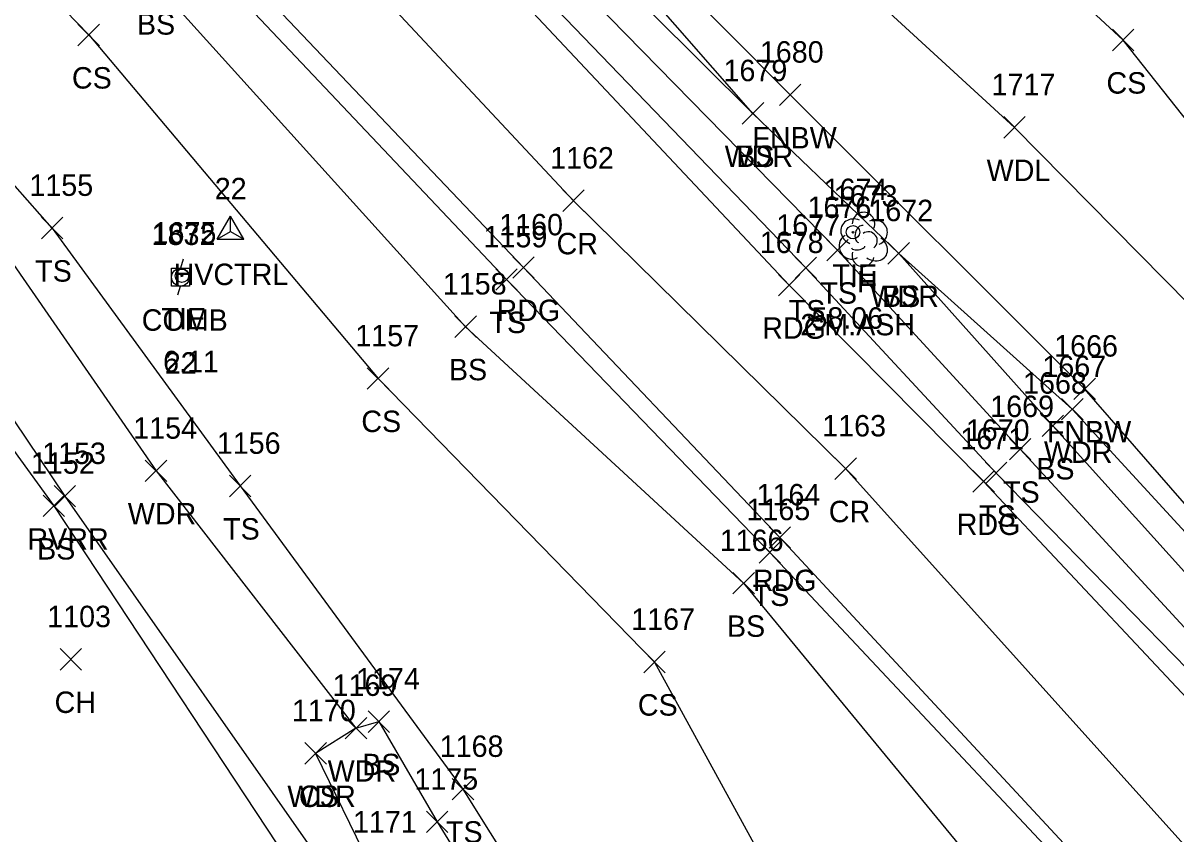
# Model space of a CAD drawing. Extents: x 1469310 to 1475157, y 493997 to 498873.
# Drawn here: x 1469401.2 to 1469508.8, y 498651.4 to 498727 of the extents above; entities that cross this region are included whole.
import ezdxf

# ---------------------------------------------------------------- set-up
doc = ezdxf.new("R2010")
doc.units = 0
for name, color, linetype in [('C_A', 7, 'Continuous'), ('C_C', 7, 'Continuous'), ('C_I', 7, 'Continuous'), ('CBP', 7, 'Continuous'), ('CPSM', 7, 'Continuous'), ('L_A', 7, 'Continuous'), ('L_C', 7, 'Continuous'), ('L_I', 7, 'Continuous'), ('L_TIC', 7, 'Continuous'), ('LAWA', 7, 'Continuous'), ('LAWE', 7, 'Continuous'), ('LELB', 7, 'Continuous'), ('LFNC', 7, 'Continuous'), ('LTD', 7, 'Continuous'), ('P_A', 7, 'Continuous'), ('P_I', 7, 'Continuous'), ('P_TIC', 7, 'Continuous'), ('PEU', 7, 'Continuous'), ('PRC', 7, 'Continuous'), ('U_A', 7, 'Continuous'), ('U_C', 7, 'Continuous'), ('U_I', 7, 'Continuous'), ('UP', 7, 'Continuous')]:
    doc.layers.add(name, color=color, linetype=linetype)

msp = doc.modelspace()

# ---------------------------------------------------------------- linework, layer by layer
at = {"layer": 'CBP'}
for centre, radius in [((1469478.65, 498707.51), 0.625), ((1469478.65, 498707.51), 0.0833), ((1469416.06, 498703.45), 0.625), ((1469416.06, 498703.45), 0.0833)]:
    msp.add_circle(centre, radius, dxfattribs=at)
at = {"layer": 'CPSM'}
for p, q in [((1469419.34, 498706.86), (1469420.59, 498709.02)), ((1469421.84, 498706.86), (1469420.59, 498709.02)), ((1469420.59, 498707.58), (1469420.59, 498709.02)), ((1469419.34, 498706.86), (1469420.59, 498707.58)), ((1469420.59, 498707.58), (1469420.59, 498707.58)), ((1469420.59, 498707.58), (1469421.84, 498706.86)), ((1469419.34, 498706.86), (1469421.84, 498706.86))]:
    msp.add_line(p, q, dxfattribs=at)
at = {"layer": 'L_TIC'}
for points in [[(1469406.36, 498724.91), (1469408.36, 498726.91)], [(1469408.36, 498724.91), (1469406.36, 498726.91)], [(1469502.85, 498724.44), (1469504.85, 498726.44)], [(1469504.85, 498724.44), (1469502.85, 498726.44)], [(1469471.78, 498719.33), (1469473.78, 498721.33)], [(1469473.78, 498719.33), (1469471.78, 498721.33)], [(1469468.32, 498717.6), (1469470.32, 498719.6)], [(1469470.32, 498717.6), (1469468.32, 498719.6)], [(1469468.32, 498717.6), (1469470.32, 498719.6)], [(1469470.32, 498717.6), (1469468.32, 498719.6)], [(1469492.7, 498716.29), (1469494.7, 498718.29)], [(1469494.7, 498716.29), (1469492.7, 498718.29)], [(1469402.96, 498706.9), (1469404.96, 498708.9)], [(1469404.96, 498706.9), (1469402.96, 498708.9)], [(1469476.2, 498704.84), (1469478.2, 498706.84)], [(1469478.2, 498704.84), (1469476.2, 498706.84)], [(1469481.91, 498704.54), (1469483.91, 498706.54)], [(1469483.91, 498704.54), (1469481.91, 498706.54)], [(1469481.91, 498704.54), (1469483.91, 498706.54)], [(1469483.91, 498704.54), (1469481.91, 498706.54)], [(1469473.24, 498703.18), (1469475.24, 498705.18)], [(1469475.24, 498703.18), (1469473.24, 498705.18)], [(1469445.33, 498702.1), (1469447.33, 498704.1)], [(1469447.33, 498702.1), (1469445.33, 498704.1)], [(1469441.52, 498697.7), (1469443.52, 498699.7)], [(1469443.52, 498697.7), (1469441.52, 498699.7)], [(1469433.35, 498692.87), (1469435.35, 498694.87)], [(1469435.35, 498692.87), (1469433.35, 498694.87)], [(1469499.25, 498691.91), (1469501.25, 498693.91)], [(1469501.25, 498691.91), (1469499.25, 498693.91)], [(1469498.1, 498690), (1469500.1, 498692)], [(1469500.1, 498690), (1469498.1, 498692)], [(1469496.29, 498688.45), (1469498.29, 498690.45)], [(1469498.29, 498688.45), (1469496.29, 498690.45)], [(1469493.24, 498686.27), (1469495.24, 498688.27)], [(1469495.24, 498686.27), (1469493.24, 498688.27)], [(1469412.64, 498684.25), (1469414.64, 498686.25)], [(1469414.64, 498684.25), (1469412.64, 498686.25)], [(1469491, 498684.05), (1469493, 498686.05)], [(1469493, 498684.05), (1469491, 498686.05)], [(1469420.49, 498682.84), (1469422.49, 498684.84)], [(1469422.49, 498682.84), (1469420.49, 498684.84)], [(1469404.14, 498681.89), (1469406.14, 498683.89)], [(1469406.14, 498681.89), (1469404.14, 498683.89)], [(1469403.11, 498680.98), (1469405.11, 498682.98)], [(1469405.11, 498680.98), (1469403.11, 498682.98)], [(1469469.89, 498676.65), (1469471.89, 498678.65)], [(1469471.89, 498676.65), (1469469.89, 498678.65)], [(1469467.45, 498673.77), (1469469.45, 498675.77)], [(1469469.45, 498673.77), (1469467.45, 498675.77)], [(1469404.7, 498666.67), (1469406.7, 498668.67)], [(1469406.7, 498666.67), (1469404.7, 498668.67)], [(1469459.14, 498666.42), (1469461.14, 498668.42)], [(1469461.14, 498666.42), (1469459.14, 498668.42)], [(1469431.29, 498660.26), (1469433.29, 498662.26)], [(1469433.29, 498660.26), (1469431.29, 498662.26)], [(1469433.43, 498660.86), (1469435.43, 498662.86)], [(1469435.43, 498660.86), (1469433.43, 498662.86)], [(1469427.53, 498657.9), (1469429.53, 498659.9)], [(1469429.53, 498657.9), (1469427.53, 498659.9)], [(1469427.53, 498657.9), (1469429.53, 498659.9)], [(1469429.53, 498657.9), (1469427.53, 498659.9)], [(1469441.27, 498654.57), (1469443.27, 498656.57)], [(1469443.27, 498654.57), (1469441.27, 498656.57)], [(1469438.87, 498651.51), (1469440.87, 498653.51)], [(1469440.87, 498651.51), (1469438.87, 498653.51)]]:
    msp.add_lwpolyline(points, dxfattribs=at)
at = {"layer": 'LAWA'}
for points in [[(1469550.26, 498635.87), (1469551.34, 498638.82), (1469543.79, 498653.66), (1469517, 498693.69), (1469493.7, 498717.29), (1469464.73, 498743.89), (1469442.45, 498767.36), (1469415.63, 498791.26), (1469396.51, 498809.17), (1469374.23, 498838.07)], [(1469550.26, 498635.87), (1469544.55, 498639.35), (1469529.26, 498656.59), (1469521.27, 498666.89), (1469499.1, 498691), (1469482.91, 498705.54), (1469469.32, 498718.6), (1469451.08, 498739.43), (1469431.27, 498758.58), (1469415.67, 498776.75), (1469392.18, 498799.73), (1469384.54, 498811.21)], [(1469393.99, 498713.68), (1469413.64, 498685.25), (1469432.29, 498661.26), (1469428.53, 498658.9)]]:
    msp.add_lwpolyline(points, dxfattribs=at)
at = {"layer": 'LAWE'}
msp.add_lwpolyline([(1469389.72, 498705.76), (1469405.14, 498682.89), (1469430.85, 498646.13), (1469451.62, 498613.53), (1469475.38, 498586.01), (1469482.32, 498572.69), (1469484.59, 498569.54), (1469489.26, 498567.84), (1469509.66, 498577.17), (1469522.84, 498580.18), (1469533.51, 498579.28), (1469530.31, 498572.64)], dxfattribs=at)
at = {"layer": 'LELB'}
for points in [[(1469689.87, 498657.87), (1469664.2, 498669.39), (1469609.73, 498671.93), (1469582.14, 498658.76), (1469563.4, 498646.02), (1469554.48, 498659.45), (1469546.06, 498676.67), (1469525.38, 498698.23), (1469503.85, 498725.44), (1469472.45, 498754.54), (1469455.13, 498777.29), (1469419.87, 498802.33), (1469400.99, 498819.04), (1469383.05, 498844.76)], [(1469469.32, 498718.6), (1469450.25, 498737.56), (1469430.69, 498757.59), (1469415.11, 498773.82), (1469391.34, 498798.74), (1469366.13, 498825.62)], [(1469596.34, 498559.71), (1469578.35, 498585.4), (1469563.74, 498607.63), (1469555.37, 498620.37), (1469550.82, 498626.65), (1469541.68, 498637.32), (1469517.52, 498662), (1469494.24, 498687.27), (1469477.2, 498705.84), (1469448.36, 498735.3), (1469427.59, 498756.34), (1469413.62, 498771.3), (1469390.02, 498797.18), (1469364.14, 498823.89)], [(1469563.74, 498607.63), (1469555.09, 498616.5), (1469548.65, 498625.25), (1469539.23, 498636.49), (1469516.21, 498660.23), (1469492, 498685.05), (1469474.24, 498704.18), (1469446.06, 498733.49), (1469425.87, 498754.55), (1469411.99, 498769.1), (1469387.95, 498794.99), (1469362.09, 498822.05)], [(1469407.36, 498725.91), (1469385.28, 498748.65)], [(1469416.82, 498734.31), (1469446.33, 498703.1), (1469470.89, 498677.65), (1469509.28, 498636.71), (1469524.42, 498615.8), (1469544.37, 498592.02), (1469564.88, 498563.16), (1469574.6, 498542.86), (1469576.57, 498532.67), (1469562.98, 498525.95), (1469548.2, 498517.37), (1469540.61, 498511.22), (1469554.07, 498484.99), (1469566.51, 498459.59)], [(1469413.42, 498730.94), (1469442.52, 498698.7), (1469468.45, 498674.77), (1469500.53, 498635.82), (1469519, 498614.53), (1469533.17, 498594.86), (1469544.52, 498587.12), (1469562.89, 498554.7), (1469567.79, 498543.52), (1469559.26, 498528.6), (1469545.4, 498521.66), (1469536.79, 498513.03)], [(1469407.36, 498725.91), (1469434.35, 498693.87), (1469460.14, 498667.42), (1469482.37, 498626.84), (1469497.15, 498602.25), (1469503.47, 498589.17)], [(1469403.96, 498707.9), (1469388.97, 498724.88)], [(1469403.96, 498707.9), (1469421.49, 498683.84), (1469442.27, 498655.57), (1469465.35, 498618.65), (1469483.42, 498593.57), (1469487.55, 498583.88), (1469493.17, 498586.36), (1469503.47, 498589.17), (1469519.52, 498592.82), (1469533.17, 498594.86)], [(1469529.26, 498656.59), (1469518.98, 498665.39), (1469497.29, 498689.45), (1469482.91, 498705.54)], [(1469387.88, 498704.33), (1469404.11, 498681.98), (1469428.9, 498644.42), (1469449.54, 498612.82), (1469474.41, 498585.16), (1469480.64, 498571.19), (1469484.92, 498567.97), (1469489.16, 498565.96), (1469510.3, 498575.29), (1469522.97, 498578.34), (1469531.66, 498578.29)], [(1469432.29, 498661.26), (1469434.43, 498661.86)], [(1469434.43, 498661.86), (1469439.87, 498652.51), (1469461.92, 498616.73), (1469481.61, 498592.39), (1469486.84, 498579.65), (1469494.02, 498578.22), (1469506.13, 498583.82), (1469519.69, 498588.79), (1469534.49, 498586.2), (1469541.72, 498579.08), (1469557.44, 498552.67)], [(1469428.53, 498658.9), (1469433.57, 498648.51), (1469459.29, 498614.44), (1469478.33, 498589.06), (1469483.97, 498576.63), (1469489.34, 498572.76), (1469492.49, 498571.98), (1469507.99, 498581.09), (1469520.42, 498585.29), (1469534.63, 498584.29), (1469538.32, 498574.02), (1469547.83, 498560.42), (1469557.44, 498552.67), (1469555.67, 498535.67), (1469539.85, 498524.73), (1469536.79, 498513.03), (1469549.04, 498482.48), (1469564.46, 498458.05), (1469576.5, 498438.75), (1469578.88, 498431.59)]]:
    msp.add_lwpolyline(points, dxfattribs=at)
at = {"layer": 'LFNC'}
msp.add_lwpolyline([(1469557.57, 498626.92), (1469550.26, 498635.87), (1469522.29, 498667.62), (1469500.25, 498692.91), (1469472.78, 498720.33), (1469454.31, 498738.91), (1469435.59, 498759.19), (1469416.3, 498780.92), (1469395.2, 498801.33), (1469384.54, 498811.21), (1469367.12, 498829.45)], dxfattribs=at)
at = {"layer": 'LTD'}
msp.add_line((1469479.59, 498706.89), (1469479.59, 498706.89), dxfattribs=at)
msp.add_line((1469479.59, 498706.89), (1469479.59, 498706.89), dxfattribs=at)
msp.add_arc((1469479.63, 498708.32), 1.05, 335.5272, 180.9563, dxfattribs=at)
for centre, major_axis, ratio, start_param, end_param in [((1469478.8, 498707.55), (1.21, -0.51), 0.895232, 1.570796, 4.712389), ((1469480.63, 498707.47), (-1.14, -0.48), 0.949671, 1.570796, 4.712389), ((1469478.5, 498706.18), (0.58, -1.04), 0.959034, 3.141593, 6.283185), ((1469479.38, 498707.34), (-0.208, -0.792), 0.645439, 3.141593, 6.283185), ((1469480.09, 498706.72), (-0.5, 0.667), 0.989748, 3.141593, 6.283185), ((1469479.13, 498706.14), (-0.625, -0.083), 0.423636, 0, 3.141593), ((1469480.59, 498706.05), (-1.09, 0.79), 0.841452, 1.570796, 4.712389), ((1469479.59, 498705.39), (0.26, 1.06), 0.942809, 1.570796, 4.712389)]:
    msp.add_ellipse(centre, major_axis=major_axis, ratio=ratio, start_param=start_param, end_param=end_param, dxfattribs=at)
at = {"layer": 'P_TIC'}
for points in [[(1469451.57, 498709.45), (1469453.57, 498711.45)], [(1469453.57, 498709.45), (1469451.57, 498711.45)], [(1469446.91, 498703.22), (1469448.91, 498705.22)], [(1469448.91, 498703.22), (1469446.91, 498705.22)], [(1469471.69, 498701.57), (1469473.69, 498703.57)], [(1469473.69, 498701.57), (1469471.69, 498703.57)], [(1469476.96, 498684.46), (1469478.96, 498686.46)], [(1469478.96, 498684.46), (1469476.96, 498686.46)], [(1469489.83, 498683.27), (1469491.83, 498685.27)], [(1469491.83, 498683.27), (1469489.83, 498685.27)], [(1469470.83, 498678.03), (1469472.83, 498680.03)], [(1469472.83, 498678.03), (1469470.83, 498680.03)]]:
    msp.add_lwpolyline(points, dxfattribs=at)
at = {"layer": 'PEU'}
for points in [[(1469787.29, 498391.19), (1469770.79, 498403.19), (1469744.94, 498420.51), (1469711.23, 498443.77), (1469680.07, 498463.21), (1469651.58, 498483.41), (1469630.63, 498501.52), (1469612.52, 498523.24), (1469599.41, 498542.19), (1469591.57, 498556.6), (1469575.61, 498583.06), (1469557.31, 498607.49), (1469540.09, 498628.65), (1469536.24, 498634.99), (1469514.98, 498658.51), (1469490.83, 498684.27), (1469472.69, 498702.57), (1469444.89, 498732.16), (1469424.97, 498753.74), (1469411.28, 498767.74), (1469386.83, 498794.07), (1469360.47, 498820.44)], [(1469418.16, 498735.54), (1469447.91, 498704.22), (1469471.83, 498679.03), (1469509.9, 498637.99), (1469529.4, 498614.8), (1469545.14, 498594.13), (1469565.65, 498563.08), (1469576.41, 498543.24), (1469581.13, 498534.68), (1469591.75, 498510.08), (1469602.71, 498485.38), (1469609.03, 498458.44), (1469615.47, 498438.56), (1469621.98, 498404.81), (1469621.72, 498400.42), (1469625.38, 498362.57), (1469626.2, 498333.72)]]:
    msp.add_lwpolyline(points, dxfattribs=at)
at = {"layer": 'PRC'}
msp.add_lwpolyline([(1469423.49, 498741.59), (1469452.57, 498710.45), (1469477.96, 498685.46), (1469512.01, 498647.6), (1469532.7, 498623.32), (1469554.78, 498596.5), (1469570.66, 498571.79), (1469585.25, 498547.18), (1469603.31, 498509.95), (1469610.7, 498488.94), (1469623.7, 498439.14), (1469630.72, 498407.83), (1469631.04, 498401.91), (1469634.46, 498363.9), (1469634.52, 498333.31)], dxfattribs=at)
at = {"layer": 'UP'}
for p, q in [((1469415.09, 498702.49), (1469415.09, 498704.16)), ((1469415.09, 498704.16), (1469416.76, 498704.16)), ((1469416.18, 498704.99), (1469415.93, 498704.16)), ((1469416.76, 498704.16), (1469416.76, 498702.49)), ((1469415.93, 498703.32), (1469415.93, 498703.32)), ((1469416.76, 498702.49), (1469415.09, 498702.49)), ((1469415.68, 498701.66), (1469415.93, 498702.49))]:
    msp.add_line(p, q, dxfattribs=at)
msp.add_circle((1469415.93, 498703.32), 0.833, dxfattribs=at)

# ---------------------------------------------------------------- texts
at = {"layer": 'C_A'}
for s, p in [('HVCTRL', (1469415.28, 498702.58)), ('TIE', (1469476.73, 498702.51)), ('TIE', (1469414.14, 498698.45))]:
    msp.add_text(s, height=2, dxfattribs=at).set_placement(p)
at = {"layer": 'C_C'}
for s, p in [('58.06', (1469474.77, 498698.51)), ('6.11', (1469414.3, 498694.45))]:
    msp.add_text(s, height=2, dxfattribs=at).set_placement(p)
at = {"layer": 'C_I'}
for s, p in [('22', (1469419.12, 498710.58)), ('1674', (1469475.91, 498710.51)), ('1675', (1469413.32, 498706.45))]:
    msp.add_text(s, height=2, dxfattribs=at).set_placement(p)
at = {"layer": 'L_A'}
for s, p in [('BS', (1469411.86, 498725.94)), ('CS', (1469405.8, 498720.91)), ('CS', (1469502.29, 498720.44)), ('FNBW', (1469469.26, 498715.33)), ('WDR', (1469466.68, 498713.6)), ('BS', (1469467.76, 498713.6)), ('WDL', (1469491.11, 498712.29)), ('TS', (1469402.37, 498702.9)), ('H', (1469479.02, 498701.89)), ('TS', (1469475.61, 498700.84)), ('WDR', (1469480.27, 498700.54)), ('BS', (1469481.35, 498700.54)), ('TS', (1469472.65, 498699.18)), ('TS', (1469444.74, 498698.1)), ('BS', (1469440.96, 498693.7)), ('CS', (1469432.79, 498688.87)), ('FNBW', (1469496.73, 498687.91)), ('WDR', (1469496.46, 498686)), ('BS', (1469495.74, 498684.45)), ('TS', (1469492.65, 498682.27)), ('WDR', (1469411.01, 498680.25)), ('TS', (1469490.41, 498680.05)), ('TS', (1469419.9, 498678.84)), ('RVRR', (1469401.65, 498677.89)), ('BS', (1469402.55, 498676.98)), ('TS', (1469469.29, 498672.65)), ('BS', (1469466.89, 498669.77)), ('CH', (1469404.18, 498662.67)), ('CS', (1469458.58, 498662.42)), ('BS', (1469432.87, 498656.86)), ('WDR', (1469429.65, 498656.26)), ('WDR', (1469425.89, 498653.9)), ('CS', (1469426.97, 498653.9)), ('TS', (1469440.68, 498650.57))]:
    msp.add_text(s, height=2, dxfattribs=at).set_placement(p)
at = {"layer": 'L_C'}
msp.add_text('2 M.ASH', height=2, dxfattribs=at).set_placement((1469473.74, 498697.89))
at = {"layer": 'L_I'}
for s, p in [('1680', (1469469.96, 498723.33)), ('1679', (1469466.57, 498721.6)), ('1679', (1469466.57, 498721.6)), ('1717', (1469491.57, 498720.29)), ('1155', (1469401.83, 498710.9)), ('1673', (1469476.85, 498709.89)), ('1676', (1469474.4, 498708.84)), ('1672', (1469480.17, 498708.54)), ('1672', (1469480.17, 498708.54)), ('1677', (1469471.5, 498707.18)), ('1159', (1469444.19, 498706.1)), ('1158', (1469440.39, 498701.7)), ('1157', (1469432.23, 498696.87)), ('1666', (1469497.41, 498695.91)), ('1667', (1469496.31, 498694)), ('1668', (1469494.51, 498692.45)), ('1669', (1469491.45, 498690.27)), ('1154', (1469411.52, 498688.25)), ('1670', (1469489.17, 498688.05)), ('1153', (1469403.02, 498685.89)), ('1156', (1469419.31, 498686.84)), ('1152', (1469401.98, 498684.98)), ('1165', (1469468.71, 498680.65)), ('1166', (1469466.22, 498677.77)), ('1103', (1469403.49, 498670.67)), ('1167', (1469457.96, 498670.42)), ('1174', (1469432.3, 498664.86)), ('1169', (1469430.11, 498664.26)), ('1170', (1469426.32, 498661.9)), ('1170', (1469426.32, 498661.9)), ('1168', (1469440.1, 498658.57)), ('1175', (1469437.74, 498655.51)), ('1171', (1469432.01, 498651.51))]:
    msp.add_text(s, height=2, dxfattribs=at).set_placement(p)
at = {"layer": 'P_A'}
for s, p in [('CR', (1469451, 498705.45)), ('RDG', (1469445.4, 498699.22)), ('RDG', (1469470.18, 498697.57)), ('CR', (1469476.39, 498680.46)), ('RDG', (1469488.32, 498679.27)), ('RDG', (1469469.31, 498674.03))]:
    msp.add_text(s, height=2, dxfattribs=at).set_placement(p)
at = {"layer": 'P_I'}
for s, p in [('1162', (1469450.4, 498713.45)), ('1160', (1469445.65, 498707.22)), ('1678', (1469469.95, 498705.57)), ('1163', (1469475.78, 498688.46)), ('1671', (1469488.66, 498687.27)), ('1164', (1469469.65, 498682.03))]:
    msp.add_text(s, height=2, dxfattribs=at).set_placement(p)
at = {"layer": 'U_A'}
msp.add_text('COMB', height=2, dxfattribs=at).set_placement((1469412.31, 498698.32))
at = {"layer": 'U_C'}
msp.add_text('22', height=2, dxfattribs=at).set_placement((1469414.46, 498694.32))
at = {"layer": 'U_I'}
msp.add_text('1832', height=2, dxfattribs=at).set_placement((1469413.23, 498706.32))

doc.saveas('drawing.dxf')
